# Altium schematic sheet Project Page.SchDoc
size A4; DocumentNumber: 2; SheetNumber: 2; SheetTotal: 5; PageSetup: Record=PageOptions¦CenterHorizontal=True¦CenterVertical=True¦PrintScale=1.00¦XCorrection=1.00¦YCorrection=1.00¦PrintKind=0¦BorderSize=5000000¦LeftOffset=0¦BottomOffset=0¦Orientation=2¦PaperLength=1000¦PaperWidth=1000¦Scale=100¦PaperSource=7¦PrintQuality=-4¦MediaType=1¦DitherType=10¦PrintScaleMode=1¦PaperKind=A4
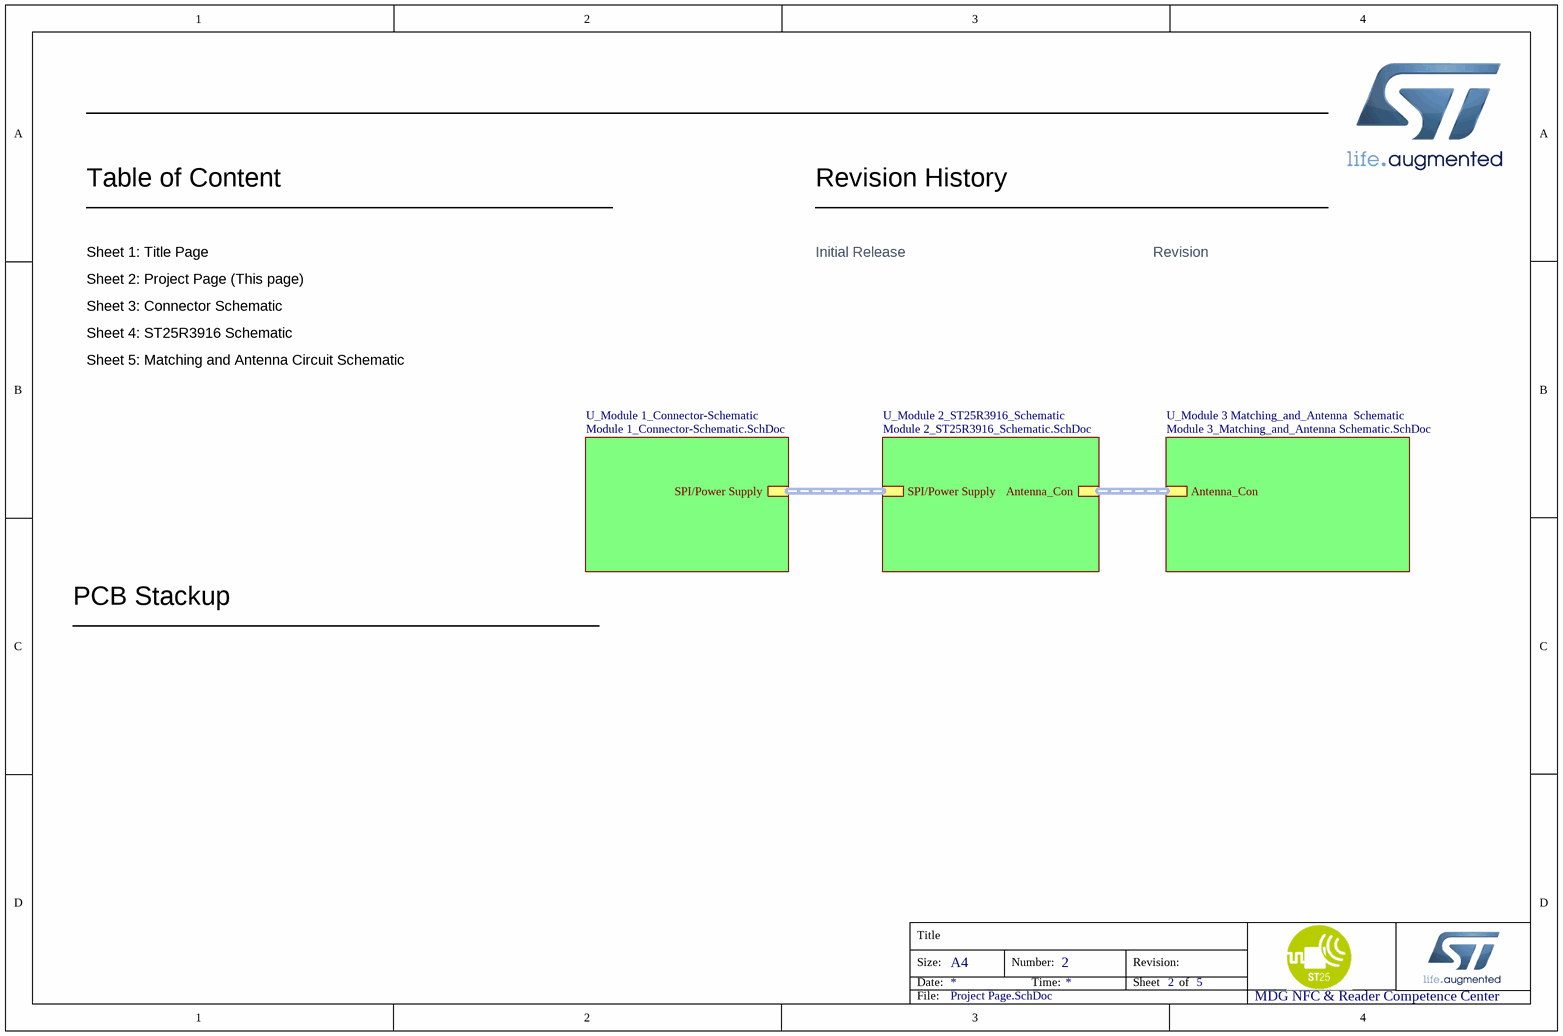
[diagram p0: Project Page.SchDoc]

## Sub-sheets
U_Module 1_Connector-Schematic = Module 1_Connector-Schematic.SchDoc: SPI/Power Supply (harness SPI/Power_Con)
U_Module 2_ST25R3916_Schematic = Module 2_ST25R3916_Schematic.SchDoc: Antenna_Con (harness Antenna_Con), SPI/Power Supply (harness SPI/Power_Con)
U_Module 3 Matching_and_Antenna  Schematic = Module 3_Matching_and_Antenna Schematic.SchDoc: Antenna_Con (harness Antenna_Con)

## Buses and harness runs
harness sheet U_Module 1_Connector-Schematic/SPI/Power Supply = sheet U_Module 2_ST25R3916_Schematic/SPI/Power Supply
harness sheet U_Module 2_ST25R3916_Schematic/Antenna_Con = sheet U_Module 3 Matching_and_Antenna  Schematic/Antenna_Con

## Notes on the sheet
- Table of Content
- Revision History
- Sheet 1: Title Page
- Sheet 2: Project Page (This page)
- Sheet 3: Connector Schematic
- Initial Release
- Revision
- Sheet 4: ST25R3916 Schematic
- Sheet 5: Matching and Antenna Circuit Schematic
- PCB Stackup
